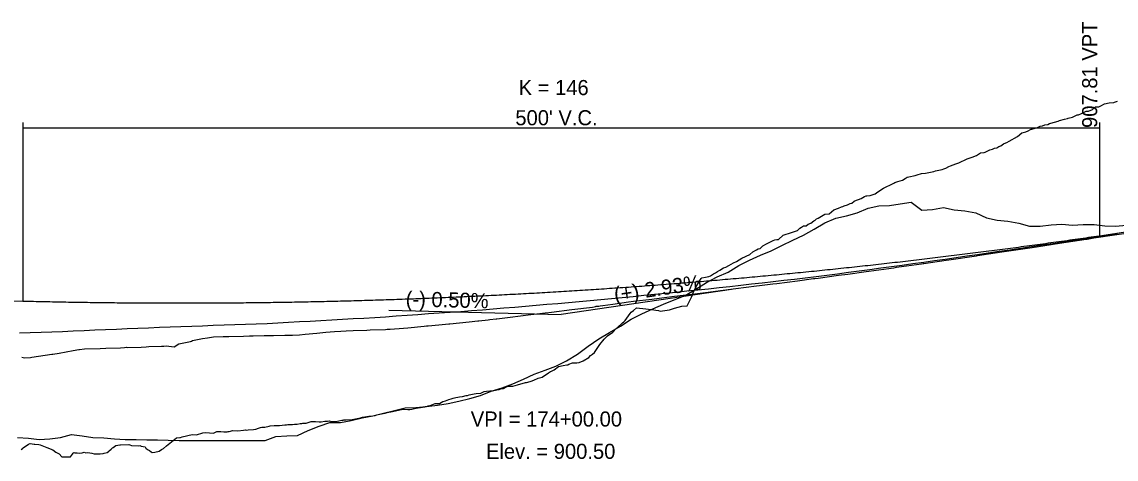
# Model space of a CAD drawing. Extents: x 1475774 to 1484571, y 1098511 to 1113011.
# Drawn here: x 1479921 to 1480429, y 1103947 to 1104150 of the extents above; entities that cross this region are included whole.
import ezdxf

# ---------------------------------------------------------------- set-up
doc = ezdxf.new("R2010")
doc.units = 0
for name, color, linetype in [('RD_DDB_GradeTX', 7, 'Continuous'), ('RD_DDB_PointTX', 7, 'Continuous'), ('RD_DDB_Profile_EX', 7, 'Continuous'), ('RD_DDB_Profile_Lbl', 7, 'Continuous'), ('RD_DDB_Profile_PR', 7, 'Continuous'), ('RD_DDB_StripGrade', 7, 'Continuous'), ('RD_DDB_VCLbl', 7, 'Continuous'), ('RD_Sketch2', 7, 'Continuous'), ('RD_Sketch3', 7, 'Continuous')]:
    doc.layers.add(name, color=color, linetype=linetype)

msp = doc.modelspace()

# ---------------------------------------------------------------- linework, layer by layer
at = {"layer": 'RD_DDB_GradeTX'}
for p in [(1480250.14, 1104025.32), (1480091.01, 1104015.75)]:
    msp.add_line(p, (1480170.98, 1104013.75), dxfattribs=at)
at = {"layer": 'RD_DDB_PointTX'}
for points in [[(1480164.42, 1104018.49), (1480169.42, 1104018.92), (1480174.42, 1104019.34), (1480179.42, 1104019.77), (1480184.42, 1104020.2), (1480189.42, 1104020.67), (1480194.42, 1104021.17), (1480199.42, 1104021.67), (1480204.42, 1104022.17), (1480209.42, 1104022.67), (1480214.42, 1104023.16), (1480219.42, 1104023.67), (1480224.42, 1104024.17), (1480229.42, 1104024.67), (1480234.42, 1104025.17), (1480239.42, 1104025.7), (1480244.42, 1104026.26), (1480249.42, 1104026.82), (1480254.42, 1104027.38), (1480259.42, 1104027.94), (1480264.42, 1104028.51), (1480269.42, 1104029.07), (1480274.42, 1104029.63), (1480279.42, 1104030.19), (1480284.42, 1104030.75), (1480289.42, 1104031.34), (1480294.42, 1104032.01), (1480299.42, 1104032.68), (1480304.42, 1104033.35), (1480309.42, 1104034.01), (1480314.42, 1104034.68), (1480319.42, 1104035.35), (1480324.42, 1104036.02), (1480329.42, 1104036.69), (1480334.42, 1104037.35), (1480339.42, 1104038.03), (1480344.42, 1104038.76), (1480349.42, 1104039.49), (1480354.42, 1104040.22), (1480359.42, 1104040.94), (1480364.42, 1104041.65), (1480369.42, 1104042.38), (1480374.42, 1104043.11), (1480379.42, 1104043.83), (1480384.42, 1104044.56), (1480389.42, 1104045.3), (1480394.42, 1104046.03), (1480399.42, 1104046.77), (1480404.42, 1104047.5), (1480409.42, 1104048.23), (1480414.42, 1104048.97), (1480419.42, 1104049.7), (1480424.42, 1104050.43), (1480429.42, 1104051.16)], [(1479919.42, 1104005.23), (1479924.42, 1104005.39), (1479929.42, 1104005.55), (1479934.42, 1104005.72), (1479939.42, 1104005.92), (1479944.42, 1104006.13), (1479949.42, 1104006.34), (1479954.42, 1104006.56), (1479959.42, 1104006.76), (1479964.42, 1104006.97), (1479969.42, 1104007.18), (1479974.42, 1104007.39), (1479979.42, 1104007.6), (1479984.42, 1104007.8), (1479989.42, 1104007.99), (1479994.42, 1104008.18), (1479999.42, 1104008.36), (1480004.42, 1104008.54), (1480009.42, 1104008.73), (1480014.42, 1104008.92), (1480019.42, 1104009.1), (1480024.42, 1104009.28), (1480029.42, 1104009.47), (1480034.42, 1104009.65), (1480039.42, 1104009.89), (1480044.42, 1104010.17), (1480049.42, 1104010.45), (1480054.42, 1104010.73), (1480059.42, 1104011.01), (1480064.42, 1104011.28), (1480069.42, 1104011.56), (1480074.42, 1104011.84), (1480079.42, 1104012.12), (1480084.42, 1104012.4), (1480089.42, 1104012.73), (1480094.42, 1104013.09), (1480099.42, 1104013.45), (1480104.42, 1104013.81), (1480109.42, 1104014.16), (1480114.42, 1104014.5), (1480119.42, 1104014.85), (1480124.42, 1104015.21), (1480129.42, 1104015.57), (1480134.42, 1104015.93), (1480139.42, 1104016.35), (1480144.42, 1104016.77), (1480149.42, 1104017.2), (1480154.42, 1104017.63), (1480159.42, 1104018.05), (1480164.42, 1104018.49)]]:
    msp.add_lwpolyline(points, dxfattribs=at)
at = {"layer": 'RD_DDB_Profile_EX'}
for points in [[(1480163.54, 1103987.94), (1480168.54, 1103989.74), (1480173.54, 1103992.2), (1480178.54, 1103995.28), (1480183.54, 1103998.98), (1480188.54, 1104002.43), (1480193.54, 1104005.34), (1480198.54, 1104008.37), (1480203.54, 1104011.52), (1480208.54, 1104014.02), (1480213.54, 1104016.31), (1480218.54, 1104018.5), (1480223.54, 1104020.51), (1480228.54, 1104022.61), (1480233.54, 1104025.54), (1480238.54, 1104028.62), (1480243.54, 1104031.23), (1480248.54, 1104033.42), (1480253.54, 1104036.46), (1480258.54, 1104038.99), (1480263.54, 1104041.29), (1480268.54, 1104043.31), (1480273.54, 1104045.78), (1480278.54, 1104048.17), (1480283.54, 1104050.53), (1480288.54, 1104053.33), (1480293.54, 1104056.28), (1480298.54, 1104058.51), (1480303.54, 1104059.61), (1480308.54, 1104060.98), (1480313.54, 1104063.06), (1480318.54, 1104064.18), (1480323.54, 1104064.39), (1480328.54, 1104065.03), (1480333.54, 1104065.88), (1480338.54, 1104062.11), (1480343.54, 1104062.4), (1480348.54, 1104063.46), (1480353.54, 1104062.3), (1480358.54, 1104061.92), (1480363.54, 1104061), (1480368.54, 1104058.6), (1480373.54, 1104057.45), (1480378.54, 1104057.06), (1480383.54, 1104056.18), (1480388.54, 1104054.73), (1480393.54, 1104054.76), (1480398.54, 1104055.37), (1480403.54, 1104055.71), (1480408.54, 1104055.26), (1480413.54, 1104055.46), (1480418.54, 1104055.55), (1480423.54, 1104054.94), (1480428.54, 1104054.8), (1480433.54, 1104055.18)], [(1479918.54, 1103956.71), (1479923.54, 1103956.34), (1479928.54, 1103955.76), (1479933.54, 1103956.04), (1479938.54, 1103956.65), (1479943.54, 1103957.99), (1479948.54, 1103957.41), (1479953.54, 1103956.7), (1479958.54, 1103956.49), (1479963.54, 1103956.07), (1479968.54, 1103955.7), (1479973.54, 1103955.69), (1479978.54, 1103955.62), (1479983.54, 1103955.53), (1479988.54, 1103955.49), (1479993.54, 1103955.25), (1479998.54, 1103955.25), (1480003.54, 1103955.25), (1480008.54, 1103955.25), (1480013.54, 1103955.25), (1480018.54, 1103955.28), (1480023.54, 1103955.25), (1480028.54, 1103955.25), (1480033.54, 1103955.25), (1480038.54, 1103957.13), (1480043.54, 1103957.44), (1480048.54, 1103957.57), (1480053.54, 1103959.86), (1480058.54, 1103961.86), (1480063.54, 1103963.65), (1480068.54, 1103963.62), (1480073.54, 1103964.58), (1480078.54, 1103965.73), (1480083.54, 1103966.7), (1480088.54, 1103967.94), (1480093.54, 1103969.25), (1480098.54, 1103970.41), (1480103.54, 1103970.63), (1480108.54, 1103971.07), (1480113.54, 1103971.7), (1480118.54, 1103972.38), (1480123.54, 1103973.5), (1480128.54, 1103974.76), (1480133.54, 1103976.19), (1480138.54, 1103978.1), (1480143.54, 1103979.79), (1480148.54, 1103981.6), (1480153.54, 1103983.72), (1480158.54, 1103986.03), (1480163.54, 1103987.94)]]:
    msp.add_lwpolyline(points, dxfattribs=at)
at = {"layer": 'RD_DDB_Profile_PR'}
for p, q in [((1480420.98, 1104050.31), (1480480.98, 1104059.09)), ((1480420.98, 1104050.31), (1480480.98, 1104059.09)), ((1479845.98, 1104021.87), (1479920.98, 1104020)), ((1479845.98, 1104021.87), (1479920.98, 1104020))]:
    msp.add_line(p, q, dxfattribs=at)
msp.add_spline([(1479920.98, 1104020), (1479930.98, 1104019.76), (1479940.98, 1104019.57), (1479950.98, 1104019.4), (1479960.98, 1104019.27), (1479970.98, 1104019.18), (1479980.98, 1104019.11), (1479990.98, 1104019.09), (1480000.98, 1104019.09), (1480010.98, 1104019.13), (1480020.98, 1104019.21), (1480030.98, 1104019.32), (1480040.98, 1104019.46), (1480050.98, 1104019.64), (1480060.98, 1104019.85), (1480070.98, 1104020.1), (1480080.98, 1104020.38), (1480090.98, 1104020.7), (1480100.98, 1104021.05), (1480110.98, 1104021.43), (1480120.98, 1104021.85), (1480130.98, 1104022.3), (1480140.98, 1104022.79), (1480150.98, 1104023.31), (1480160.98, 1104023.86), (1480170.98, 1104024.45), (1480180.98, 1104025.07), (1480190.98, 1104025.73), (1480200.98, 1104026.42), (1480210.98, 1104027.15), (1480220.98, 1104027.91), (1480230.98, 1104028.7), (1480240.98, 1104029.53), (1480250.98, 1104030.4), (1480260.98, 1104031.29), (1480270.98, 1104032.23), (1480280.98, 1104033.19), (1480290.98, 1104034.19), (1480300.98, 1104035.23), (1480310.98, 1104036.29), (1480320.98, 1104037.4), (1480330.98, 1104038.53), (1480340.98, 1104039.71), (1480350.98, 1104040.91), (1480360.98, 1104042.15), (1480370.98, 1104043.43), (1480380.98, 1104044.73), (1480390.98, 1104046.08), (1480400.98, 1104047.45), (1480410.98, 1104048.86), (1480420.98, 1104050.31)], degree=3, dxfattribs=at)
msp.add_spline([(1479920.98, 1104020), (1479930.98, 1104019.76), (1479940.98, 1104019.57), (1479950.98, 1104019.4), (1479960.98, 1104019.27), (1479970.98, 1104019.18), (1479980.98, 1104019.11), (1479990.98, 1104019.09), (1480000.98, 1104019.09), (1480010.98, 1104019.13), (1480020.98, 1104019.21), (1480030.98, 1104019.32), (1480040.98, 1104019.46), (1480050.98, 1104019.64), (1480060.98, 1104019.85), (1480070.98, 1104020.1), (1480080.98, 1104020.38), (1480090.98, 1104020.7), (1480100.98, 1104021.05), (1480110.98, 1104021.43), (1480120.98, 1104021.85), (1480130.98, 1104022.3), (1480140.98, 1104022.79), (1480150.98, 1104023.31), (1480160.98, 1104023.86), (1480170.98, 1104024.45), (1480180.98, 1104025.07), (1480190.98, 1104025.73), (1480200.98, 1104026.42), (1480210.98, 1104027.15), (1480220.98, 1104027.91), (1480230.98, 1104028.7), (1480240.98, 1104029.53), (1480250.98, 1104030.4), (1480260.98, 1104031.29), (1480270.98, 1104032.23), (1480280.98, 1104033.19), (1480290.98, 1104034.19), (1480300.98, 1104035.23), (1480310.98, 1104036.29), (1480320.98, 1104037.4), (1480330.98, 1104038.53), (1480340.98, 1104039.71), (1480350.98, 1104040.91), (1480360.98, 1104042.15), (1480370.98, 1104043.43), (1480380.98, 1104044.73), (1480390.98, 1104046.08), (1480400.98, 1104047.45), (1480410.98, 1104048.86), (1480420.98, 1104050.31)], degree=3, dxfattribs=at)
at = {"layer": 'RD_DDB_VCLbl'}
for p, q in [((1479920.98, 1104102.81), (1479920.98, 1104020)), ((1480420.98, 1104102.81), (1480420.98, 1104050.31)), ((1479920.98, 1104100.31), (1480420.98, 1104100.31))]:
    msp.add_line(p, q, dxfattribs=at)
at = {"layer": 'RD_Sketch2'}
msp.add_lwpolyline([(1479920.52, 1103993.91), (1479921.1, 1103993.82), (1479921.88, 1103993.63), (1479924.61, 1103993.79), (1479925.21, 1103993.96), (1479928.25, 1103994.44), (1479934.43, 1103995.35), (1479934.87, 1103995.37), (1479937.78, 1103995.88), (1479944.41, 1103997.07), (1479946.99, 1103997.52), (1479947.3, 1103997.55), (1479949.55, 1103997.77), (1479956.83, 1103998.03), (1479959.46, 1103998.1), (1479966.36, 1103998.35), (1479968.16, 1103998.41), (1479969.09, 1103998.54), (1479969.45, 1103998.49), (1479975.89, 1103998.62), (1479978.31, 1103998.67), (1479979.46, 1103998.9), (1479985.42, 1103999.08), (1479986.49, 1103999.11), (1479987.8, 1103999.19), (1479988.81, 1103999.05), (1479991.29, 1103998.81), (1479993.36, 1104000.07), (1479994.94, 1104000.42), (1479998.84, 1104001.26), (1479999.34, 1104001.45), (1479999.73, 1104001.61), (1480004.47, 1104002.54), (1480006.67, 1104002.97), (1480009.49, 1104003.35), (1480014, 1104003.48), (1480016.72, 1104003.57), (1480023.53, 1104003.77), (1480026.21, 1104003.85), (1480027.38, 1104003.9), (1480027.95, 1104003.91), (1480033.06, 1104003.98), (1480037.4, 1104004.04), (1480042.59, 1104004.11), (1480046.15, 1104004.16), (1480049.48, 1104004.39), (1480052.11, 1104004.63), (1480057.52, 1104005.12), (1480061.64, 1104005.49), (1480065.71, 1104005.87), (1480068.64, 1104005.94), (1480071.17, 1104006.12), (1480074.44, 1104006.35), (1480080.7, 1104006.54), (1480082.28, 1104006.59), (1480089.41, 1104006.82), (1480090.23, 1104006.87), (1480091.64, 1104006.97), (1480097.83, 1104007.41), (1480099.76, 1104007.59), (1480107.33, 1104008.34), (1480108.54, 1104008.45), (1480109.28, 1104008.52), (1480114.2, 1104008.96), (1480118.81, 1104009.38), (1480119.38, 1104009.43), (1480128.34, 1104010.34), (1480132.25, 1104010.74), (1480132.79, 1104010.8), (1480137.13, 1104011.31), (1480137.87, 1104011.4), (1480140.78, 1104011.74), (1480141.09, 1104011.78), (1480147.4, 1104012.54), (1480156.93, 1104013.7), (1480158.31, 1104013.87), (1480161.1, 1104014.25), (1480163.56, 1104014.56), (1480165.36, 1104014.68), (1480166.45, 1104014.81), (1480175.98, 1104016), (1480185.51, 1104017.19), (1480186.34, 1104017.29), (1480186.99, 1104017.46), (1480187.34, 1104017.56), (1480188.09, 1104017.65), (1480188.44, 1104017.67), (1480189.15, 1104017.7), (1480190.33, 1104017.95), (1480195.04, 1104018.6), (1480202.34, 1104019.61), (1480204.57, 1104019.89), (1480213.1, 1104020.94), (1480214.14, 1104021.05), (1480223.62, 1104022.2), (1480233.15, 1104023.36), (1480238.04, 1104023.95), (1480241.6, 1104024.37), (1480242.68, 1104024.51), (1480252.21, 1104025.77), (1480261.74, 1104027.02), (1480263.09, 1104027.2), (1480269.39, 1104027.94), (1480271.26, 1104028.18), (1480280.79, 1104029.43), (1480288.14, 1104030.39), (1480288.55, 1104030.44), (1480288.87, 1104030.48), (1480290.32, 1104030.67), (1480299.85, 1104031.96), (1480304.11, 1104032.53), (1480312.67, 1104033.72), (1480313.92, 1104033.89), (1480325.49, 1104035.46), (1480326.78, 1104035.64), (1480338.32, 1104037.24), (1480339.08, 1104037.34), (1480339.39, 1104037.39), (1480349.79, 1104038.91), (1480351.14, 1104039.11), (1480363.96, 1104041.04), (1480364.44, 1104041.11), (1480372.55, 1104042.3), (1480376.79, 1104042.94), (1480389.75, 1104044.88), (1480395.66, 1104045.8), (1480402.43, 1104046.83), (1480414.82, 1104048.7), (1480415.25, 1104048.76), (1480418.45, 1104049.26), (1480428.08, 1104050.71), (1480439.91, 1104052.49)], dxfattribs=at)
at = {"layer": 'RD_Sketch3'}
msp.add_lwpolyline([(1479920.16, 1103951.14), (1479920.77, 1103951.52), (1479921.13, 1103951.9), (1479923.53, 1103953.6), (1479924.31, 1103953.85), (1479926.17, 1103953.56), (1479926.53, 1103953.5), (1479928.37, 1103953.36), (1479928.99, 1103953.31), (1479931.42, 1103952.41), (1479932.14, 1103952.01), (1479934.92, 1103950.94), (1479936.24, 1103949.85), (1479937.78, 1103949.11), (1479939.1, 1103947.71), (1479940.72, 1103947.71), (1479941.92, 1103947.71), (1479943.08, 1103947.71), (1479944.01, 1103948.9), (1479944.32, 1103949.43), (1479944.66, 1103949.64), (1479945.15, 1103949.62), (1479946.26, 1103949.57), (1479947.5, 1103949.41), (1479948.58, 1103949.6), (1479949.47, 1103949.82), (1479950.28, 1103949.63), (1479951.05, 1103949.74), (1479952.16, 1103949.59), (1479953.03, 1103949.43), (1479954.09, 1103949.15), (1479955.22, 1103949.11), (1479955.7, 1103949.09), (1479956.1, 1103949.09), (1479956.83, 1103949.13), (1479958.31, 1103949.21), (1479958.75, 1103949.4), (1479960.08, 1103949.76), (1479960.69, 1103950.22), (1479961.15, 1103950.53), (1479962.04, 1103951.3), (1479962.6, 1103951.85), (1479962.98, 1103952.1), (1479964.2, 1103952.96), (1479965.98, 1103953.33), (1479966.36, 1103953.33), (1479970.2, 1103953.37), (1479970.66, 1103953.3), (1479971.46, 1103952.92), (1479974.8, 1103952.77), (1479975.33, 1103953.03), (1479975.89, 1103952.61), (1479977.74, 1103952.38), (1479978.15, 1103951.74), (1479978.81, 1103951.15), (1479979.73, 1103950.71), (1479980.53, 1103949.98), (1479981.07, 1103949.74), (1479982.27, 1103949.88), (1479984.3, 1103950.39), (1479985.42, 1103951.09), (1479986.28, 1103951.64), (1479987.69, 1103952.8), (1479992.3, 1103956.48), (1479993.88, 1103956.74), (1479994.27, 1103956.71), (1479994.94, 1103956.94), (1479999.67, 1103958.01), (1480001.6, 1103957.96), (1480004.6, 1103958.87), (1480005.88, 1103959.03), (1480009.46, 1103958.67), (1480011.1, 1103959.44), (1480012.93, 1103959.45), (1480014.26, 1103959.23), (1480015.95, 1103959.3), (1480016.39, 1103959.4), (1480016.74, 1103959.47), (1480018.52, 1103959.91), (1480020.8, 1103959.76), (1480023.53, 1103960.14), (1480024.36, 1103960.26), (1480024.92, 1103960.01), (1480025.64, 1103960.2), (1480028.17, 1103960.43), (1480029.19, 1103960.55), (1480030.49, 1103961.06), (1480031.32, 1103961.24), (1480031.98, 1103961.4), (1480033.06, 1103961.45), (1480033.45, 1103961.47), (1480035.33, 1103961.96), (1480035.79, 1103962.03), (1480037.72, 1103962.18), (1480039.85, 1103962.17), (1480040.16, 1103962.21), (1480042.59, 1103962.48), (1480043.42, 1103962.57), (1480044.12, 1103962.64), (1480045, 1103962.68), (1480046.25, 1103962.7), (1480047.23, 1103962.81), (1480048.38, 1103962.91), (1480049.83, 1103963.1), (1480050.51, 1103963.2), (1480051.05, 1103963.26), (1480052.11, 1103963.35), (1480052.64, 1103963.39), (1480054.86, 1103964.15), (1480056.91, 1103964.14), (1480058.68, 1103963.96), (1480059.04, 1103963.94), (1480059.49, 1103963.91), (1480061.17, 1103964.2), (1480061.64, 1103964.19), (1480062.5, 1103964.18), (1480063.3, 1103964.44), (1480064.32, 1103964.14), (1480066.32, 1103964.11), (1480069.14, 1103964.7), (1480069.7, 1103964.78), (1480070.14, 1103964.8), (1480071.17, 1103964.85), (1480073.98, 1103965), (1480077.79, 1103965.83), (1480078.78, 1103966.09), (1480080.7, 1103966.37), (1480081.61, 1103966.5), (1480082.49, 1103966.55), (1480083.59, 1103966.7), (1480084.62, 1103966.91), (1480085.44, 1103967.15), (1480086.75, 1103967.53), (1480088.41, 1103967.82), (1480088.88, 1103967.89), (1480089.26, 1103968.02), (1480090.23, 1103968.25), (1480092.6, 1103968.81), (1480093.22, 1103968.93), (1480096.92, 1103969.68), (1480098.02, 1103969.86), (1480099.76, 1103969.73), (1480100.75, 1103969.65), (1480101.67, 1103969.8), (1480102.83, 1103970.12), (1480104.58, 1103970.51), (1480107.63, 1103970.96), (1480108.06, 1103970.99), (1480108.41, 1103971.03), (1480109.28, 1103971.29), (1480110.2, 1103971.57), (1480112.43, 1103972.5), (1480114.46, 1103972.52), (1480116.07, 1103973.33), (1480117.23, 1103973.75), (1480118.81, 1103974.25), (1480119.91, 1103974.6), (1480120.85, 1103974.87), (1480122.03, 1103975.19), (1480122.98, 1103975.32), (1480123.74, 1103975.56), (1480125.11, 1103975.77), (1480126.82, 1103976.11), (1480127.24, 1103976.16), (1480127.58, 1103976.23), (1480128.34, 1103976.41), (1480130.65, 1103976.95), (1480131.61, 1103977.14), (1480133.63, 1103977.3), (1480135.26, 1103977.96), (1480136.4, 1103978.22), (1480137.87, 1103978.32), (1480139.09, 1103978.4), (1480141.18, 1103978.84), (1480142.15, 1103979.02), (1480142.94, 1103979.19), (1480144.28, 1103979.48), (1480145.96, 1103980.31), (1480146.78, 1103980.52), (1480147.4, 1103980.49), (1480148.54, 1103980.44), (1480150.74, 1103981.08), (1480154.46, 1103982.23), (1480154.93, 1103982.17), (1480155.52, 1103982.35), (1480157.06, 1103982.84), (1480158.31, 1103983.31), (1480160.3, 1103984.13), (1480162.15, 1103984.72), (1480165.07, 1103986.62), (1480165.58, 1103986.99), (1480166, 1103987.26), (1480166.45, 1103987.47), (1480167.71, 1103988.04), (1480169.85, 1103989.55), (1480171.97, 1103990.12), (1480173.7, 1103990.38), (1480174.1, 1103990.46), (1480174.61, 1103990.64), (1480176.23, 1103991.25), (1480177.54, 1103991.37), (1480178.36, 1103991.31), (1480179.37, 1103991.48), (1480181.21, 1103992.18), (1480183.82, 1103993.82), (1480184.63, 1103994.65), (1480185.51, 1103995.35), (1480186.55, 1103996.18), (1480187.66, 1103997.97), (1480189.03, 1103999.88), (1480190.96, 1104002.3), (1480192.56, 1104003.9), (1480195.04, 1104005.55), (1480196.51, 1104007.18), (1480197.14, 1104007.73), (1480199.57, 1104009.83), (1480200.16, 1104010.34), (1480200.67, 1104011), (1480202.99, 1104014.21), (1480203.55, 1104014.79), (1480204.57, 1104015.66), (1480205.98, 1104016.84), (1480210.37, 1104016.34), (1480214.09, 1104015.91), (1480215.02, 1104015.8), (1480216.3, 1104015.61), (1480217.07, 1104015.37), (1480221.27, 1104015.99), (1480223.62, 1104016.64), (1480227.13, 1104017.6), (1480229.61, 1104017.73), (1480230.78, 1104020.21), (1480231.48, 1104021.85), (1480232.38, 1104023.8), (1480233.15, 1104025.45), (1480233.47, 1104026.12), (1480235.06, 1104029.02), (1480236.01, 1104030.52), (1480236.39, 1104030.83), (1480238.07, 1104031.12), (1480239.57, 1104031.37), (1480240.39, 1104031.74), (1480241.84, 1104032.59), (1480242.68, 1104033.14), (1480243.55, 1104033.72), (1480244.66, 1104034.3), (1480246.48, 1104035.38), (1480247.47, 1104035.64), (1480248.95, 1104036.49), (1480251.12, 1104037.75), (1480252.5, 1104038.35), (1480255, 1104039.91), (1480258.63, 1104041.59), (1480260.02, 1104042.76), (1480261.74, 1104043.82), (1480262.5, 1104044.29), (1480263.51, 1104044.42), (1480264.74, 1104045.61), (1480266.38, 1104046.56), (1480269.46, 1104048.02), (1480270.25, 1104048.39), (1480271.26, 1104048.48), (1480272.02, 1104048.55), (1480274.17, 1104050.49), (1480278.01, 1104051.74), (1480278.89, 1104052.16), (1480280.79, 1104052.74), (1480281.88, 1104053.79), (1480282.66, 1104054.26), (1480283.6, 1104054.9), (1480284.79, 1104054.96), (1480285.76, 1104055.72), (1480286.92, 1104056.18), (1480288.31, 1104057.25), (1480289.04, 1104057.45), (1480289.64, 1104058.09), (1480290.32, 1104058.5), (1480293.53, 1104060.31), (1480295.42, 1104060.4), (1480297.73, 1104062.38), (1480299.85, 1104063.02), (1480301.29, 1104063.73), (1480301.81, 1104063.85), (1480302.44, 1104064.2), (1480303.95, 1104064.6), (1480305.19, 1104065.28), (1480306.08, 1104065.48), (1480307.16, 1104066.36), (1480308.21, 1104066.8), (1480309.08, 1104067.17), (1480310.34, 1104067.58), (1480311.87, 1104068.48), (1480312.67, 1104068.75), (1480312.97, 1104068.85), (1480314.61, 1104068.98), (1480316.87, 1104069.76), (1480318.13, 1104070.63), (1480320.76, 1104072.39), (1480321.32, 1104072.62), (1480324.65, 1104074.25), (1480325.49, 1104074.7), (1480326.04, 1104074.98), (1480327.41, 1104075.5), (1480328.54, 1104075.85), (1480329.54, 1104076.07), (1480330.76, 1104076.91), (1480331.68, 1104077.48), (1480332.43, 1104077.68), (1480335.49, 1104078.32), (1480336.32, 1104078.52), (1480338.32, 1104079.14), (1480340.22, 1104079.35), (1480344.09, 1104080.18), (1480344.94, 1104080.35), (1480347.98, 1104081.09), (1480348.74, 1104081.41), (1480349.67, 1104081.69), (1480351.14, 1104082.38), (1480351.87, 1104082.67), (1480354.4, 1104083.6), (1480355.75, 1104084.19), (1480359.64, 1104086.06), (1480361.95, 1104086.82), (1480363.96, 1104087.58), (1480365.81, 1104088.81), (1480367.41, 1104088.94), (1480367.95, 1104089.12), (1480368.6, 1104089.32), (1480370.08, 1104090.15), (1480371.29, 1104090.51), (1480372.21, 1104090.98), (1480373.34, 1104091.15), (1480374.35, 1104091.65), (1480375.17, 1104091.98), (1480376.48, 1104092.9), (1480376.79, 1104093.04), (1480378.07, 1104093.62), (1480379.06, 1104094.23), (1480382.94, 1104096.34), (1480385.02, 1104098), (1480386.82, 1104098.55), (1480387.15, 1104098.73), (1480387.55, 1104098.85), (1480389.28, 1104099.68), (1480389.61, 1104099.76), (1480390.7, 1104100.03), (1480392.29, 1104100.51), (1480393.55, 1104101.17), (1480394.58, 1104101.24), (1480395.69, 1104101.7), (1480397.04, 1104101.96), (1480397.82, 1104102.38), (1480398.46, 1104102.5), (1480401.78, 1104103.54), (1480402.43, 1104103.73), (1480404.85, 1104104.34), (1480406.22, 1104104.74), (1480406.52, 1104104.82), (1480408.49, 1104105.27), (1480410.1, 1104106.17), (1480410.62, 1104106.4), (1480411.27, 1104106.45), (1480412.76, 1104107.04), (1480413.97, 1104107.61), (1480414.89, 1104108.14), (1480415.25, 1104108.15), (1480416.02, 1104108.17), (1480417.85, 1104108.88), (1480419.16, 1104110.1), (1480420.77, 1104110.16), (1480421.72, 1104110.55), (1480423.43, 1104111.49), (1480425.6, 1104112.02), (1480427.7, 1104112.17), (1480428.08, 1104112.3), (1480429.48, 1104112.8)], dxfattribs=at)

# ---------------------------------------------------------------- texts
at = {"layer": 'RD_DDB_GradeTX'}
for s, rotation, p in [('(+) 2.93%', 8.3205, (1480196.1, 1104019.44)), ('(-) 0.50%', 358.5679, (1480098.74, 1104017.55))]:
    msp.add_text(s, height=7, rotation=rotation, dxfattribs=at).set_placement(p)
at = {"layer": 'RD_DDB_Profile_Lbl'}
for s, p in [('VPI = 174+00.00', (1480129.02, 1103961.75)), ('Elev. = 900.50', (1480136.09, 1103946.75))]:
    msp.add_text(s, height=7, dxfattribs=at).set_placement(p)
at = {"layer": 'RD_DDB_StripGrade'}
msp.add_text('907.81 VPT', height=7, rotation=90, dxfattribs=at).set_placement((1480419.98, 1104100.31))
at = {"layer": 'RD_DDB_VCLbl'}
for s, p in [('K = 146', (1480151.26, 1104115.56)), ("500' V.C.", (1480149.73, 1104101.56))]:
    msp.add_text(s, height=7, dxfattribs=at).set_placement(p)

doc.saveas('drawing.dxf')
